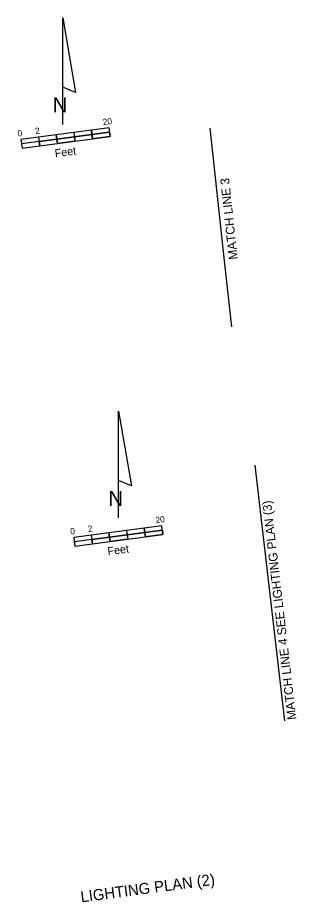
# Model space of a CAD drawing. Extents: x 927695 to 927982, y 636546 to 636800.
# Drawn here: x 927919.1 to 927981.8, y 636600.9 to 636800 of the extents above; entities that cross this region are included whole.
import ezdxf

# ---------------------------------------------------------------- set-up
doc = ezdxf.new("R2010")
doc.units = 0
for name, color, linetype in [('MatchLines_dp', 7, 'Continuous'), ('NorthArw_dp', 7, 'Continuous'), ('Scale_dp', 7, 'Continuous'), ('TextMisc', 7, 'Continuous')]:
    doc.layers.add(name, color=color, linetype=linetype)

msp = doc.modelspace()

# ---------------------------------------------------------------- linework, layer by layer
at = {"layer": 'MatchLines_dp'}
for points in [[(927967.25, 636730.38), (927965.64, 636745.29), (927962.44, 636775.12)], [(927979.25, 636641.76), (927978.27, 636650.13), (927972.55, 636699.25)]]:
    msp.add_lwpolyline(points, dxfattribs=at)
at = {"layer": 'NorthArw_dp'}
for p, q in [((927929.24, 636775.96), (927929.24, 636799.96)), ((927941.79, 636687.4), (927941.79, 636711.4))]:
    msp.add_line(p, q, dxfattribs=at)
for points in [[(927929.24, 636784.36), (927929.24, 636799.96), (927932.12, 636783.16)], [(927941.79, 636695.8), (927941.79, 636711.4), (927944.67, 636694.6)]]:
    msp.add_lwpolyline(points, close=True, dxfattribs=at)
at = {"layer": 'Scale_dp'}
for p, q in [((927939.64, 636775.18), (927919.81, 636772.55)), ((927939.9, 636773.2), (927939.64, 636775.18)), ((927939.77, 636774.19), (927919.94, 636771.56)), ((927920.07, 636770.57), (927939.9, 636773.2)), ((927923.77, 636773.08), (927924.04, 636771.1)), ((927927.74, 636773.6), (927928, 636771.62)), ((927931.7, 636774.13), (927931.97, 636772.15)), ((927935.67, 636774.66), (927935.93, 636772.67)), ((927919.81, 636772.55), (927920.07, 636770.57)), ((927951.52, 636685.66), (927931.69, 636683.03)), ((927951.78, 636683.68), (927951.52, 636685.66)), ((927951.65, 636684.67), (927931.82, 636682.04)), ((927931.95, 636681.05), (927951.78, 636683.68)), ((927935.65, 636683.56), (927935.92, 636681.58)), ((927939.62, 636684.08), (927939.88, 636682.1)), ((927943.58, 636684.61), (927943.85, 636682.63)), ((927947.55, 636685.14), (927947.81, 636683.15)), ((927931.69, 636683.03), (927931.95, 636681.05))]:
    msp.add_line(p, q, dxfattribs=at)
for points in [[(927923.91, 636772.09), (927927.87, 636772.61), (927927.74, 636773.6), (927923.77, 636773.08)], [(927927.87, 636772.61), (927931.84, 636773.14), (927931.97, 636772.15), (927928, 636771.62)], [(927931.84, 636773.14), (927935.8, 636773.67), (927935.67, 636774.66), (927931.7, 636774.13)], [(927935.8, 636773.67), (927939.77, 636774.19), (927939.9, 636773.2), (927935.93, 636772.67)], [(927920.07, 636770.57), (927924.04, 636771.1), (927923.91, 636772.09), (927919.94, 636771.56)], [(927935.79, 636682.57), (927939.75, 636683.09), (927939.62, 636684.08), (927935.65, 636683.56)], [(927939.75, 636683.09), (927943.72, 636683.62), (927943.85, 636682.63), (927939.88, 636682.1)], [(927943.72, 636683.62), (927947.68, 636684.15), (927947.55, 636685.14), (927943.58, 636684.61)], [(927947.68, 636684.15), (927951.65, 636684.67), (927951.78, 636683.68), (927947.81, 636683.15)], [(927931.95, 636681.05), (927935.92, 636681.58), (927935.79, 636682.57), (927931.82, 636682.04)]]:
    msp.add_lwpolyline(points, close=True, dxfattribs=at)

# ---------------------------------------------------------------- texts
at = {"layer": 'MatchLines_dp'}
for s, rotation, p in [('MATCH LINE 3', 96.1345, (927968.62, 636745.64)), ('MATCH LINE 4 SEE LIGHTING PLAN (3)', 96.6513, (927981.83, 636642.11))]:
    msp.add_text(s, height=2, rotation=rotation, dxfattribs=at).set_placement(p)
at = {"layer": 'NorthArw_dp'}
for p in [(927926.96, 636778.68), (927939.51, 636690.12)]:
    msp.add_text('N', height=3.36, dxfattribs=at).set_placement(p)
at = {"layer": 'Scale_dp'}
for s, height, p in [('20', 1.4, (927938.31, 636775.76)), ('2', 1.4, (927923.09, 636773.74)), ('0', 1.4, (927919.13, 636773.22)), ('Feet', 1.8, (927927.54, 636768.53)), ('20', 1.4, (927950.19, 636686.24)), ('0', 1.4, (927931.01, 636683.7)), ('2', 1.4, (927934.97, 636684.22)), ('Feet', 1.8, (927939.42, 636679.01))]:
    msp.add_text(s, height=height, rotation=7.5594, dxfattribs=at).set_placement(p)
at = {"layer": 'TextMisc'}
msp.add_text('      LIGHTING PLAN (2)        ', height=2.5, rotation=7.5594, dxfattribs=at).set_placement((927927.87, 636600.17))

doc.saveas('drawing.dxf')
